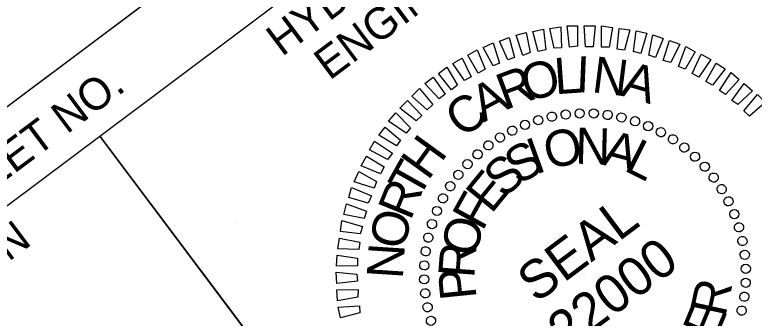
# Model space of a CAD drawing. Extents: x 2186558 to 2188589, y 629855 to 631741.
# Drawn here: x 2187861 to 2187977.7, y 631594 to 631641.9 of the extents above; entities that cross this region are included whole.
import ezdxf

# ---------------------------------------------------------------- set-up
doc = ezdxf.new("R2010")
doc.units = 0
doc.layers.add('Default', color=7, linetype='Continuous')
doc.layers.add('Sheet Plan CELL', color=7, linetype='Continuous')

msp = doc.modelspace()

# ---------------------------------------------------------------- linework, layer by layer
at = {"layer": 'Default'}
for p, q in [((2187952.34, 631626.38), (2187952.34, 631626.38)), ((2187958.85, 631625.12), (2187958.85, 631625.12)), ((2187960.95, 631624.35), (2187960.95, 631624.35)), ((2187939.47, 631623.62), (2187939.47, 631623.62)), ((2187962.94, 631623.38), (2187962.94, 631623.38)), ((2187964.85, 631622.28), (2187964.85, 631622.28)), ((2187966.65, 631620.97), (2187966.65, 631620.97)), ((2187968.32, 631619.51), (2187968.32, 631619.51)), ((2187932.43, 631618.33), (2187932.43, 631618.33)), ((2187969.87, 631617.95), (2187969.87, 631617.95)), ((2187930.96, 631616.66), (2187930.96, 631616.66)), ((2187971.29, 631616.23), (2187971.29, 631616.23)), ((2187929.65, 631614.86), (2187929.65, 631614.86)), ((2187972.54, 631614.38), (2187972.54, 631614.38)), ((2187928.55, 631612.96), (2187928.55, 631612.96)), ((2187973.61, 631612.46), (2187973.61, 631612.46)), ((2187974.55, 631610.45), (2187974.55, 631610.45)), ((2187895.81, 631609.02), (2187895.81, 631609.02)), ((2187975.3, 631608.35), (2187975.3, 631608.35)), ((2187975.82, 631606.21), (2187975.82, 631606.21)), ((2187925.8, 631604.56), (2187925.8, 631604.56)), ((2187976.2, 631604.03), (2187976.2, 631604.03)), ((2187925.56, 631602.36), (2187925.56, 631602.36)), ((2187976.35, 631601.8), (2187976.35, 631601.8)), ((2187950.96, 631600.97), (2187950.96, 631600.97)), ((2187925.57, 631600.15), (2187925.57, 631600.15)), ((2187976.36, 631599.59), (2187976.36, 631599.59)), ((2187925.72, 631597.92), (2187925.72, 631597.92)), ((2187976.12, 631597.39), (2187976.12, 631597.39)), ((2187926.09, 631595.73), (2187926.09, 631595.73)), ((2187975.74, 631595.2), (2187975.74, 631595.2))]:
    msp.add_line(p, q, dxfattribs=at)
for points in [[(2187948.51, 631636.8), (2187948.13, 631640.18), (2187949.79, 631640.16), (2187949.77, 631636.98)], [(2187951.05, 631636.87), (2187950.84, 631640.19), (2187952.57, 631640.16), (2187952.25, 631636.88)], [(2187953.57, 631636.8), (2187953.58, 631640.16), (2187955.28, 631639.92), (2187954.77, 631636.81)], [(2187941.13, 631635.5), (2187940.11, 631638.72), (2187941.65, 631639.11), (2187942.31, 631635.94)], [(2187943.57, 631636.13), (2187942.72, 631639.28), (2187944.4, 631639.66), (2187944.76, 631636.39)], [(2187946.1, 631636.63), (2187945.39, 631639.77), (2187947.16, 631640.02), (2187947.24, 631636.72)], [(2187956.06, 631636.51), (2187956.35, 631639.76), (2187958.05, 631639.52), (2187957.2, 631636.35)], [(2187958.62, 631636.15), (2187959.04, 631639.38), (2187960.72, 631639), (2187959.76, 631635.81)], [(2187938.79, 631634.82), (2187937.47, 631637.75), (2187939, 631638.33), (2187939.85, 631635.17)], [(2187961.03, 631635.55), (2187961.66, 631638.75), (2187963.31, 631638.16), (2187962.09, 631635.15)], [(2187963.32, 631634.68), (2187964.29, 631637.87), (2187965.94, 631637.28), (2187964.51, 631634.37)], [(2187936.48, 631633.85), (2187934.87, 631636.75), (2187936.46, 631637.5), (2187937.49, 631634.28)], [(2187965.72, 631633.76), (2187966.86, 631636.89), (2187968.37, 631636.06), (2187966.79, 631633.36)], [(2187934.11, 631632.7), (2187932.49, 631635.54), (2187933.95, 631636.38), (2187935.18, 631633.31)], [(2187967.88, 631632.66), (2187969.29, 631635.68), (2187970.8, 631634.85), (2187968.95, 631632.07)], [(2187931.96, 631631.53), (2187930.1, 631634.25), (2187931.59, 631635.05), (2187933.02, 631632.13)], [(2187970.05, 631631.37), (2187971.66, 631634.29), (2187973.08, 631633.4), (2187971.09, 631630.83)], [(2187929.87, 631630.09), (2187927.82, 631632.66), (2187929.15, 631633.66), (2187930.84, 631630.82)], [(2187927.93, 631628.63), (2187925.67, 631631.05), (2187927.01, 631632.05), (2187928.9, 631629.36)], [(2187972.19, 631629.95), (2187974.02, 631632.83), (2187975.3, 631631.71), (2187973.12, 631629.31)], [(2187974.14, 631628.37), (2187976.08, 631631.09), (2187977.4, 631629.93), (2187975.06, 631627.73)], [(2187926.06, 631626.91), (2187923.66, 631629.09), (2187924.84, 631630.3), (2187926.94, 631627.76)], [(2187976, 631626.73), (2187978.18, 631629.31), (2187979.37, 631628.05), (2187976.93, 631625.91)], [(2187924.32, 631625.17), (2187921.72, 631627.2), (2187922.94, 631628.37), (2187925.21, 631626.02)], [(2187922.75, 631623.22), (2187919.94, 631625.1), (2187921.1, 631626.42), (2187923.44, 631624.06)], [(2187921.23, 631621.2), (2187918.43, 631622.9), (2187919.41, 631624.2), (2187921.87, 631622.12)], [(2187919.8, 631619.05), (2187916.94, 631620.58), (2187917.75, 631621.95), (2187920.56, 631620.06)], [(2187918.69, 631616.82), (2187915.65, 631618.09), (2187916.48, 631619.6), (2187919.27, 631617.9)], [(2187917.68, 631614.54), (2187914.53, 631615.54), (2187915.26, 631617.17), (2187918.08, 631615.61)], [(2187916.72, 631612.18), (2187913.67, 631613.05), (2187914.11, 631614.65), (2187917.25, 631613.34)], [(2187916.13, 631609.77), (2187912.89, 631610.38), (2187913.34, 631612.05), (2187916.47, 631610.92)], [(2187915.49, 631607.33), (2187912.36, 631607.71), (2187912.6, 631609.41), (2187915.83, 631608.48)], [(2187915.25, 631604.87), (2187911.97, 631604.94), (2187912.21, 631606.65), (2187915.41, 631606.01)], [(2187915.06, 631602.26), (2187911.72, 631602.23), (2187911.83, 631603.95), (2187915.05, 631603.46)], [(2187915.04, 631599.84), (2187911.81, 631599.51), (2187911.69, 631601.26), (2187914.94, 631600.98)], [(2187915.11, 631597.3), (2187911.92, 631596.74), (2187911.81, 631598.49), (2187915.14, 631598.53)], [(2187915.44, 631594.83), (2187912.4, 631594.07), (2187912.03, 631595.75), (2187915.35, 631595.96)]]:
    msp.add_lwpolyline(points, close=True, dxfattribs=at)
for centre, major_axis in [((2187945.73, 631625.82), (-0.15, 0.713)), ((2187947.92, 631626.18), (-0.087, 0.724)), ((2187950.12, 631626.35), (-0.024, 0.729)), ((2187952.34, 631626.33), (0.04, 0.728)), ((2187954.54, 631626.11), (0.103, 0.722)), ((2187956.72, 631625.7), (0.165, 0.71)), ((2187941.49, 631624.54), (-0.272, 0.676)), ((2187943.58, 631625.27), (-0.212, 0.698)), ((2187958.86, 631625.11), (0.227, 0.693)), ((2187960.93, 631624.33), (0.286, 0.67)), ((2187939.48, 631623.62), (-0.33, 0.65)), ((2187962.93, 631623.37), (0.344, 0.643)), ((2187937.55, 631622.54), (-0.385, 0.619)), ((2187964.83, 631622.24), (0.398, 0.611)), ((2187935.72, 631621.29), (-0.438, 0.583)), ((2187966.63, 631620.95), (0.45, 0.574)), ((2187934.01, 631619.88), (-0.487, 0.543)), ((2187968.32, 631619.51), (0.498, 0.532)), ((2187932.42, 631618.33), (-0.532, 0.498)), ((2187969.86, 631617.93), (0.543, 0.487)), ((2187930.98, 631616.65), (-0.574, 0.45)), ((2187971.27, 631616.21), (0.583, 0.438)), ((2187929.69, 631614.85), (-0.611, 0.398)), ((2187972.52, 631614.39), (0.619, 0.385)), ((2187928.56, 631612.94), (-0.643, 0.344)), ((2187973.61, 631612.46), (0.65, 0.33)), ((2187927.6, 631610.94), (-0.67, 0.286)), ((2187974.52, 631610.44), (0.676, 0.272)), ((2187926.82, 631608.87), (-0.693, 0.227)), ((2187975.26, 631608.35), (0.698, 0.212)), ((2187926.23, 631606.74), (-0.71, 0.165)), ((2187975.81, 631606.2), (0.713, 0.15)), ((2187925.82, 631604.56), (-0.722, 0.103)), ((2187976.17, 631604.02), (0.724, 0.087)), ((2187925.6, 631602.35), (-0.728, 0.04)), ((2187976.34, 631601.81), (0.729, 0.024)), ((2187925.58, 631600.14), (-0.729, -0.024)), ((2187976.32, 631599.59), (0.728, -0.04)), ((2187925.75, 631597.93), (-0.724, -0.087)), ((2187976.1, 631597.39), (0.722, -0.103)), ((2187926.11, 631595.74), (-0.713, -0.15)), ((2187975.69, 631595.21), (0.71, -0.165)), ((2187926.66, 631593.6), (-0.698, -0.212))]:
    msp.add_ellipse(centre, major_axis=major_axis, ratio=0.999708, dxfattribs=at)
at = {"layer": 'Sheet Plan CELL'}
for p, q in [((2187786.86, 631572.75), (2187946.9, 631692.76)), ((2187786.86, 631572.75), (2187946.9, 631692.76)), ((2187874.4, 631622.77), (2187941.88, 631532.8))]:
    msp.add_line(p, q, dxfattribs=at)
for points in [[(2187771.81, 631592.82), (2187931.9, 631712.82), (2187946.9, 631692.76), (2187786.86, 631572.75)], [(2187874.4, 631622.77), (2187954.4, 631682.76), (2188021.9, 631592.74), (2187941.9, 631532.75)], [(2187794.35, 631562.75), (2187874.4, 631622.77), (2187941.9, 631532.75), (2187861.84, 631472.76)]]:
    msp.add_lwpolyline(points, close=True, dxfattribs=at)

# ---------------------------------------------------------------- texts
at = {"layer": 'Default'}
for s, height, rotation, p in [('O', 5.71, 13.4799, (2187941.66, 631628.2)), ('L', 5.71, 3.9719, (2187946.28, 631629.36)), ('I', 5.71, 357.6139, (2187949.45, 631629.7)), ('N', 5.71, 352.7296, (2187951.9, 631629.73)), ('R', 5.71, 20.5564, (2187938.37, 631626.84)), ('A', 5.71, 343.719, (2187956.4, 631629.23)), ('A', 5.71, 28.4433, (2187934.94, 631624.87)), ('C', 5.71, 36.7724, (2187931.65, 631622.3)), ('O', 5.71, 12.5944, (2187945.16, 631617.49)), ('N', 5.71, 358.4518, (2187949.37, 631618.41)), ('H', 5.71, 54.0385, (2187926.19, 631615.61)), ('A', 5.71, 345.0491, (2187953.46, 631618.3)), ('S', 5.71, 30.2481, (2187940.43, 631614.96)), ('I', 5.71, 19.8594, (2187943.12, 631616.63)), ('L', 5.71, 333.3178, (2187956.93, 631617.43)), ('T', 5.71, 60.7096, (2187924.66, 631612.63)), ('S', 5.71, 40.6368, (2187938.08, 631612.83)), ('E', 5.71, 50.8337, (2187936.18, 631610.36)), ('R', 5.71, 67.786, (2187923.42, 631609.3)), ('F', 5.71, 60.9484, (2187934.76, 631607.62)), ('SEAL', 6.073, 36.8829, (2187943.28, 631596.28)), ('O', 5.71, 77.2941, (2187922.42, 631604.64)), ('O', 5.71, 75.0909, (2187933.63, 631603.46)), ('022000', 6.075, 36.8829, (2187944.42, 631586)), ('N', 5.71, 86.3047, (2187922.2, 631600.12)), ('R', 5.71, 85.6166, (2187933.47, 631600.25)), ('P', 5.71, 95.8135, (2187933.87, 631597.17)), ('R', 5.71, 77.6979, (2187973.09, 631594.05)), ('E', 5.71, 67.501, (2187971.51, 631590.24))]:
    msp.add_text(s, height=height, rotation=rotation, dxfattribs=at).set_placement(p)
at = {"layer": 'Sheet Plan CELL'}
for s, height, p in [('HYDRAULICS', 5, (2187903.14, 631635.22)), ('ENGINEER', 5, (2187910.66, 631631.47)), ('PROJECT REFERENCE NO.', 5.0001, (2187794.81, 631599.15)), ('R/W SHEET NO.', 5.0001, (2187837.98, 631599.59)), ('ROADWAY DESIGN', 5.0001, (2187814.23, 631568.54))]:
    msp.add_text(s, height=height, rotation=36.8593, dxfattribs=at).set_placement(p)

doc.saveas('drawing.dxf')
